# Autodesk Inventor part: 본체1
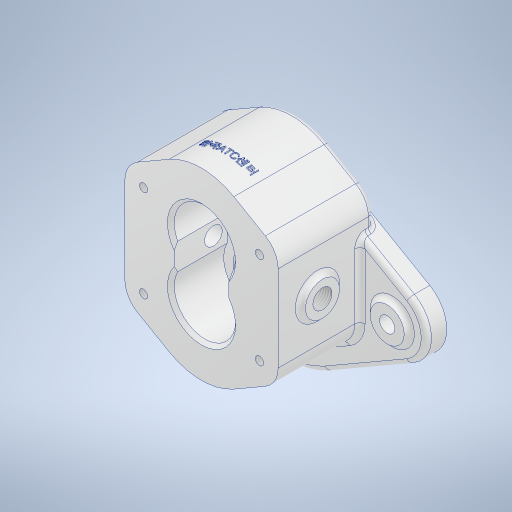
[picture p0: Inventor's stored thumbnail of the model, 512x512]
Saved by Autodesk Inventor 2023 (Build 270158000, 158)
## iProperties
Created: 2025-11
Part Number: 본체1
Material: 알루미늄 6061
Document SubType Name: Modeling
Designer: home
Mass: 1255.67 g
Surface Area: 576.33 cm^2
Volume: 465.061 cm^3
Density: 2.7 g/cm^3
Appearance: 알루미늄 - 평지
Author: home
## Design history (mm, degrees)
sketch "스케치1"
  geometry: L1 (26, 45.033)-(74, 17.321); L2 (26, -45.033)-(74, -17.321); L3 (0, 52)-(0, -52); L4 (-26, 45.033)-(-74, 17.321); L5 (-26, -45.033)-(-74, -17.321); C1 r 10 at (-64, 0); C2 r 10 at (64, 0); A1 r 52 centre (0, 0) between (26, 45.033) and (-26, 45.033); A2 r 20 centre (64, 0) between (74, -17.321) and (74, 17.321); A3 r 20 centre (-64, 0) between (-74, 17.321) and (-74, -17.321); A4 r 52 centre (0, 0) between (-26, -45.033) and (26, -45.033); 4 further points
  constraints: 14 point on circle, 10 end point, 6 centre point, 6 tangent, 5 symmetric about line, 2 coincident, 2 horizontal alignment, 1 equal radius, 1 midpoint, 1 vertical, 1 other
  dimensions: "d0" = 168 distance of point (-84, 0) point (84, 0); "d1" = 128 distance of C1.centre C2.centre; "d2" = 64 distance from line of C1.centre L3; "d3" = 20 radius of A3; "d5" = 20 diameter of C2; "d33" = 52 radius of A1
extrude "돌출1" new body sketch "스케치1" distance "d6" = 15; taper "d7" = 0 deg
extrude "돌출2" join sketch "스케치1" distance "d8" = 12; taper "d9" = 0 deg
fillet "모깎기1" dims "d10" = 3
sketch "스케치2"
  geometry: C1 r 10 at (0, 0) reference; C2 r 10 at (128, 0) reference; 3 further points
  constraints: 2 coincident
hole "구멍1" sketch "스케치2" at (0, 0), (128, 0) diameter "d11" = 9; stored, may be unused: countersink angle "d15" = 90 deg, drill point angle "d17" = 0 deg; dims "d12" = 12, "d13" = 4, "d14" = 2, "d16" = 16
sketch "스케치3"
  geometry: C1 r 25 at (0, 0)
  constraints: 1 centre point
  dimensions: "d18" = 50 diameter of C1
extrude "돌출3" join sketch "스케치3" distance "d19" = 4; taper "d20" = 0 deg
node "작업 평면1"
sketch "스케치4"
  geometry: L1 (19, 64.909)-(37.5, 54.228); L2 (45, 41.238)-(45, -9.238); L3 (37.5, -22.228)-(19, -32.909); L4 (0, -111.174)-(0, 92.407); L5 (-19, 64.909)-(-37.5, 54.228); L6 (-45, 41.238)-(-45, -9.238); L7 (-37.5, -22.228)-(-19, -32.909); L8 (0, 0)-(45, 0); A1 r 38 centre (0, 32) between (19, 64.909) and (-19, 64.909); A2 r 38 centre (0, 0) between (-19, -32.909) and (19, -32.909); A3 r 15 centre (30, 41.238) between (45, 41.238) and (37.5, 54.228); A4 r 15 centre (-30, 41.238) between (-37.5, 54.228) and (-45, 41.238); A5 r 15 centre (-30, -9.238) between (-45, -9.238) and (-37.5, -22.228); A6 r 15 centre (30, -9.238) between (37.5, -22.228) and (45, -9.238); 4 further points
  constraints: 16 end point, 12 point on circle, 12 tangent, 11 point on line, 6 centre point, 4 equal radius, 2 symmetric about line, 1 parallel, 1 perpendicular, 1 vertical
  dimensions: "d22" = 90 distance between parallel lines of L2 L6; "d24" = 38 radius of A2; "d25" = 15 radius of A3; "d27" = 60 deg angle of L3 L1; "d28" = 30 deg angle of L3 L8; "d39" = 32 distance of L8.start A1.centre
fillet "모깎기2" dims "d30" = 3
extrude "돌출4" join sketch "스케치4" distance "d31" = 56; taper "d32" = 0 deg
sketch "스케치9"
  geometry: L1 (-9.238, 60)-(41.238, 60) reference; C1 r 10 at (16, 37); 1 further point
  constraints: 1 centre point
  dimensions: "d74" = 23 distance from line of L1 C1.centre; "d75" = 16 horizontal distance of point (0, 0) C1.centre; "d76" = 20 diameter of C1
extrude "돌출7" join sketch "스케치9" stored distance "d77" = 96; taper "d78" = 0 deg
sketch "스케치7"
  geometry: L1 (32, 60)-(32, 0); L2 (0, -4)-(0, 60); L3 (94.4, 60)-(-76.4, 60) reference; L4 (17.321, 0)-(45.033, 0) reference; L5 (-25, -4)-(25, -4) reference; L6 (52, 0)-(45.033, 0) reference; L7 (32, 60)-(50, 60); L8 (41.238, 60)-(54.228, 60) reference; L9 (50, 29)-(44.5, 29); L10 (43.5, 28)-(43.5, 14); L11 (43.5, 14)-(32, 14); L12 (50, 29)-(50, 60); L13 (44.5, 29)-(43.5, 28); L14 (-15, -3.3)-(-15, 3); L15 (-14.7, 3.3)-(-10.5, 3.3); L16 (-10.5, 3.3)-(-10.5, 14); L17 (-10.5, 14)-(-11.5, 14); L18 (-11.5, 14)-(-11.5, 28); L19 (-12.5, 29)-(-18, 29); L20 (-18, 29)-(-18, 60); L21 (-32.909, 60)-(-22.228, 60) reference; L22 (0, 60)-(-18, 60); L23 (-11.5, 28)-(-12.5, 29); L24 (0, -4)-(-15.404, -4); L25 (-15, -3.3)-(-15.404, -4); A1 r 0.3 centre (-14.7, 3) between (-14.7, 3.3) and (-15, 3); 4 further points
  constraints: 39 end point, 12 point on line, 7 vertical, 4 perpendicular, 2 midpoint, 2 point on circle, 2 tangent, 1 centre point, 1 collinear, 1 horizontal, 1 parallel
  dimensions: "d46" = 32 distance between parallel lines of L2 L1; "d47" = 31 distance of L9.start L7.end; "d48" = 15 distance of point (43.5, 29) L10.end; "d49" = 36 diameter of L12 L1; "d50" = 23 diameter of L10 L1; "d51" = 1 distance of L9.end point (43.5, 29); "d52" = 45 deg angle of L9 L13; "d53" = 31 distance of L19.end L20.end; "d54" = 15 distance of L17.end point (-11.5, 29); "d56" = 30 diameter of L14 L2; "d57" = 21 diameter of L16 L2; "d58" = 23 diameter of L18 point (0, 28); "d59" = 36 diameter of L20 L2; "d60" = 1 distance of L18.end point (-11.5, 29); "d61" = 45 deg angle of L18 L23; "d62" = 7.3 distance between parallel lines of L15 L5; "d63" = 30 deg angle of L25 L14; "d64" = 0.7 distance from line of L24 L14.start; "d65" = 0.3 radius of A1
revolve "회전1" stored, may be unused: angle "d66" = 90 deg
revolve "회전2" stored, may be unused: angle "d67" = 360 deg
chamfer "모따기1" distance "d68" = 2; stored, may be unused: second distance "d69" = 2, angle "d70" = 45 deg
sketch "스케치8"
  geometry: L1 (16, 0)-(-16, 0); L2 (-16, 0)-(-16, 32); L3 (-16, 32)-(16, 32); L4 (16, 32)-(16, 0); A1 r 38 centre (0, 0) between (-19, -32.909) and (19, -32.909) reference; A2 r 20 centre (0, 32) between (12, 16) and (-12, 16) reference; 1 further point
  constraints: 8 end point, 2 midpoint, 2 parallel, 1 coincident, 1 horizontal, 1 perpendicular
  dimensions: "d71" = 32 distance of L2.end L3.end
extrude "돌출6" cut sketch "스케치8" stored distance "d72" = 10; taper "d73" = 0 deg
fillet "모깎기4" dims "d79" = 3
fillet "모깎기5" dims "d80" = 3
fillet "모깎기6" dims "d81" = 3
fillet "모깎기7" dims "d82" = 3
sketch "스케치10"
  geometry: C1 r 10 at (0, 0) reference; 2 further points
  constraints: 1 coincident
hole "구멍2" sketch "스케치10" at (0, 0) diameter "d83" = 10.5; stored, may be unused: countersink angle "d89" = 90 deg, drill point angle "d91" = 0 deg; dims "d84" = 11, "d85" = 0.62479, "d86" = 10.589, "d87" = 4, "d88" = 2, "d90" = 8
sketch "스케치11"
  geometry: L1 (-30, 41.238)-(30, -9.238); L2 (30, -9.238)-(-30, -9.238); L3 (-30, -9.238)-(30, 41.238); L4 (-34, -11)-(34, -11); L5 (34, -11)-(34, 43); L6 (34, 43)-(-34, 43); L7 (-34, 43)-(-34, -11); L8 (-34, -11)-(34, 43); L9 (34, -11)-(-34, 43); C1 r 15.404 at (0, 0) reference; A1 r 15 centre (30, 41.238) between (45, 41.238) and (37.5, 54.228) reference; A2 r 15 centre (-30, 41.238) between (-37.5, 54.228) and (-45, 41.238) reference; A3 r 15 centre (-30, -9.238) between (-45, -9.238) and (-37.5, -22.228) reference; A4 r 38 centre (0, 0) between (-19, -32.909) and (19, -32.909) reference; 6 further points
  constraints: 18 end point, 4 coincident, 4 midpoint, 2 horizontal, 2 parallel, 1 perpendicular
  dimensions: "d92" = 68 distance of L5.end L6.end; "d93" = 54 distance of L6.end L4.start; "d94" = 16 distance of A4.centre point (0, 16)
hole "구멍3" sketch "스케치11" at (-34, 43), (-34, -11), (34, -11), (34, 43) diameter "d95" = 4.917; stored, may be unused: countersink angle "d99" = 90 deg, drill point angle "d101" = 118 deg; dims "d96" = 12, "d97" = 4, "d98" = 2, "d100" = 14
node "작업 평면2"
sketch "스케치12"
  geometry: L1 (-19, 0)-(19, 0) reference; 2 further points
  constraints: 1 vertical alignment, 1 other
  dimensions: "d102" = 16 distance from line of L1 point (0, -16)
feature "엠보싱1" sketch "스케치12" dims "d103" = 0.5, "d104" = 0
node "솔리드1"
mirror "미러1"
feature "A9D066F2-1C7D-4E18-AEED-F7BC21143FA4" dims "d11" = 9, "d12" = 12, "d13" = 4, "d14" = 2, "d15" = 90 deg, "d16" = 16, "d17" = 0
other parameters: "d21" = -64
